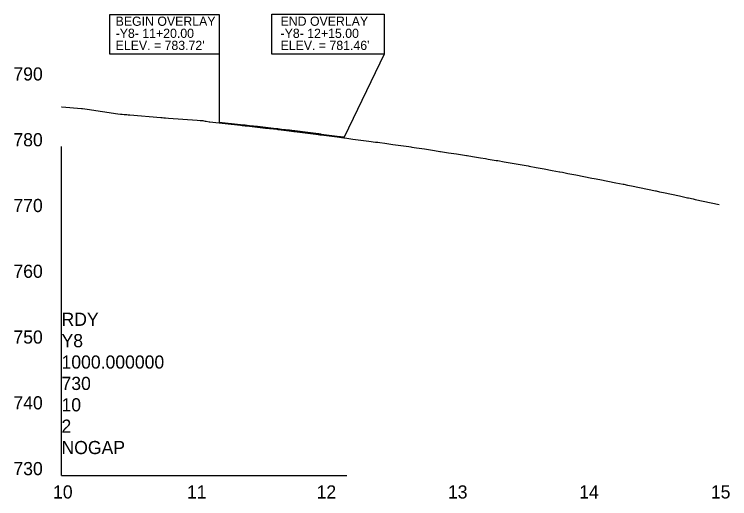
# Model space of a CAD drawing. Extents: x 579185 to 595036, y -53221 to -44640.
# Drawn here: x 589792 to 590335, y -49553 to -49185 of the extents above; entities that cross this region are included whole.
import ezdxf

# ---------------------------------------------------------------- set-up
doc = ezdxf.new("R2010")
doc.units = 0
for name, color, linetype in [('Exist Profile Cell', 7, 'Continuous'), ('Exist Vertical Profile Ground Line', 7, 'Continuous'), ('Exist Vertical Profile Horizontal Axis Label Major', 7, 'Continuous'), ('Exist Vertical Profile Vertical Axis Label', 7, 'Continuous'), ('Prop Grid Mask', 7, 'Continuous'), ('Prop Vertical Profile Curve Label', 7, 'Continuous'), ('Prop Vertical Profile Grade', 7, 'Continuous'), ('Prop VPI Label', 7, 'Continuous')]:
    doc.layers.add(name, color=color, linetype=linetype)

msp = doc.modelspace()

# ---------------------------------------------------------------- linework, layer by layer
at = {"layer": 'Exist Profile Cell'}
for q in [(589827.43, -49285.12), (590044.43, -49535.12), (589827.43, -49535.12)]:
    msp.add_line((589827.43, -49535.12), q, dxfattribs=at)
at = {"layer": 'Exist Vertical Profile Ground Line'}
for points in [[(589827.43, -49254.83), (589827.74, -49254.86), (589842.7, -49256.06), (589843.49, -49256.13), (589846.96, -49256.68), (589870.31, -49260.14), (589872.41, -49260.35), (589872.96, -49260.4), (589873.52, -49260.46), (589875.02, -49260.58), (589877.11, -49260.78), (589878.23, -49260.89), (589879.38, -49261.01), (589902.89, -49262.87), (589903.45, -49262.93), (589904.03, -49262.99), (589905.27, -49263.12), (589906.58, -49263.25), (589908.87, -49263.49), (589930.63, -49265.06), (589932.79, -49265.14), (589934.82, -49265.21), (589935.61, -49265.49), (589936.54, -49265.65), (589937.5, -49265.72), (589939.73, -49266.17), (589940.22, -49266.36), (589963.56, -49268.91), (589964.79, -49269.05), (589966.08, -49269.16), (589966.97, -49269.26), (589970.34, -49269.63), (589976.39, -49270.3), (589982.45, -49270.97), (589988.5, -49271.64), (589991.04, -49271.92), (589991.91, -49272.02), (589994.55, -49272.35), (590000.61, -49273.09), (590004.2, -49273.54), (590004.81, -49273.6), (590006.66, -49273.83), (590012.71, -49274.6), (590018.77, -49275.37), (590022.69, -49275.87), (590023.44, -49275.97), (590023.82, -49276.03), (590024.21, -49276.09), (590024.82, -49276.17), (590030.88, -49276.95), (590036.93, -49277.73), (590042.04, -49278.39), (590042.6, -49278.49), (590042.98, -49278.55), (590049.04, -49279.34), (590055.09, -49280.14), (590061.14, -49280.94), (590066.22, -49281.61), (590067.2, -49281.74), (590067.83, -49281.83), (590069.37, -49282.04), (590073.25, -49282.57), (590079.31, -49283.42), (590085.36, -49284.26), (590091.41, -49285.1), (590093.05, -49285.33), (590093.78, -49285.45), (590097.47, -49286.01), (590103.52, -49286.92), (590109.58, -49287.84), (590113.83, -49288.48), (590115.15, -49288.7), (590115.63, -49288.78), (590121.68, -49289.74), (590127.74, -49290.71), (590133.79, -49291.67), (590135.42, -49291.93), (590135.75, -49291.99), (590139.84, -49292.65), (590145.9, -49293.63), (590149.85, -49294.27), (590151.95, -49294.62), (590158.01, -49295.61), (590158.75, -49295.73), (590159.09, -49295.78), (590164.06, -49296.64), (590170.11, -49297.69), (590176.17, -49298.73), (590182.22, -49299.78), (590183.03, -49299.93), (590188.28, -49300.91), (590194.33, -49302.04), (590200.38, -49303.17), (590206.08, -49304.24), (590206.44, -49304.3), (590208.25, -49304.63), (590212.49, -49305.46), (590218.54, -49306.63), (590224.6, -49307.81), (590230.72, -49309), (590232.47, -49309.36)], [(590232.47, -49309.36), (590236.71, -49310.18), (590242.76, -49311.36), (590248.81, -49312.55), (590254.52, -49313.66), (590254.87, -49313.73), (590257.9, -49314.36), (590260.92, -49314.98), (590266.98, -49316.22), (590273.03, -49317.47), (590279.08, -49318.71), (590279.63, -49318.82), (590282.17, -49319.36), (590285.14, -49320), (590291.19, -49321.32), (590297.24, -49322.63), (590303.3, -49323.94), (590304.28, -49324.16), (590307.6, -49324.88), (590309.35, -49325.26), (590315.41, -49326.58), (590321.46, -49327.9), (590327.52, -49329.21)]]:
    msp.add_lwpolyline(points, dxfattribs=at)
at = {"layer": 'Prop Grid Mask'}
for points in [[(589864.2, -49184.73), (589947.43, -49184.73), (589947.43, -49214.72), (589864.2, -49214.72)], [(589987.43, -49184.53), (590072.82, -49184.53), (590072.82, -49214.72), (589987.43, -49214.72)]]:
    msp.add_lwpolyline(points, close=True, dxfattribs=at)
at = {"layer": 'Prop Vertical Profile Curve Label'}
for p, q in [((589947.43, -49214.72), (589947.43, -49266.52)), ((590072.82, -49214.72), (590042.43, -49277.83))]:
    msp.add_line(p, q, dxfattribs=at)
at = {"layer": 'Prop Vertical Profile Grade'}
msp.add_lwpolyline([(589947.43, -49266.52), (589963.63, -49268.29), (589964.85, -49268.43), (589966.14, -49268.54), (589967.04, -49268.64), (589970.41, -49269.01), (589976.46, -49269.68), (589982.51, -49270.35), (589988.57, -49271.02), (589991.11, -49271.3), (589991.99, -49271.4), (589994.63, -49271.73), (590000.68, -49272.47), (590004.27, -49272.92), (590004.89, -49272.98), (590006.74, -49273.21), (590012.79, -49273.98), (590018.85, -49274.75), (590022.77, -49275.25), (590023.53, -49275.35), (590023.92, -49275.41), (590024.3, -49275.47), (590024.9, -49275.55), (590030.96, -49276.33), (590037.01, -49277.11), (590042.13, -49277.77), (590042.43, -49277.83)], dxfattribs=at)

# ---------------------------------------------------------------- texts
at = {"layer": 'Exist Profile Cell'}
for s, p in [('RDY', (589827.43, -49421.37)), ('Y8', (589827.43, -49437.62)), ('1000.000000', (589827.43, -49453.87)), ('730', (589827.43, -49470.12)), ('10', (589827.43, -49486.37)), ('2', (589827.43, -49502.62)), ('NOGAP', (589827.43, -49518.87))]:
    msp.add_text(s, height=10, dxfattribs=at).set_placement(p)
at = {"layer": 'Exist Vertical Profile Horizontal Axis Label Major'}
for s, p in [('10', (589821.01, -49552.62)), ('11', (589922.85, -49552.62)), ('12', (590021.4, -49552.62)), ('13', (590121.23, -49552.62)), ('14', (590221.07, -49552.62)), ('15', (590321.17, -49552.62))]:
    msp.add_text(s, height=10, dxfattribs=at).set_placement(p)
at = {"layer": 'Exist Vertical Profile Vertical Axis Label'}
for s, p in [('790', (589790.86, -49234.87)), ('780', (589790.86, -49284.87)), ('770', (589790.86, -49334.87)), ('760', (589790.86, -49384.87)), ('750', (589790.86, -49434.87)), ('740', (589790.86, -49484.87)), ('730', (589790.86, -49534.87))]:
    msp.add_text(s, height=10, dxfattribs=at).set_placement(p)
at = {"layer": 'Prop VPI Label'}
for s, p in [('BEGIN OVERLAY', (589868.58, -49193.29)), ('END OVERLAY', (589993.98, -49193.29)), ('-Y8- 11+20.00', (589868.58, -49202.47)), ('-Y8- 12+15.00', (589993.98, -49202.47)), ("ELEV. = 783.72'", (589868.58, -49211.65)), ("ELEV. = 781.46'", (589993.98, -49211.65))]:
    msp.add_text(s, height=7, dxfattribs=at).set_placement(p)

doc.saveas('drawing.dxf')
